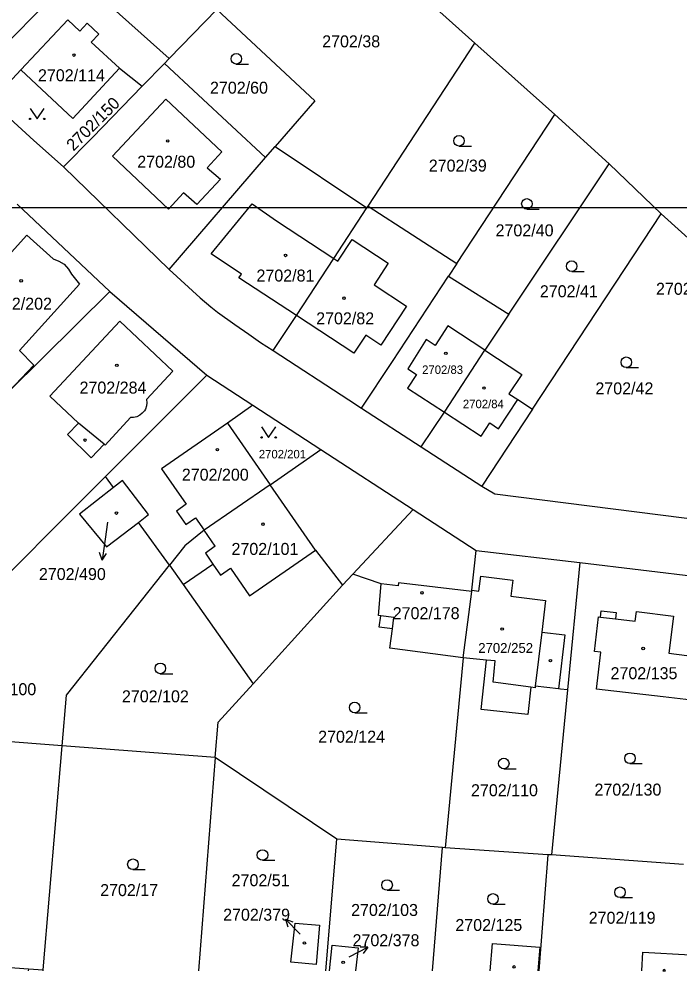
# Model space of a CAD drawing. Extents: x -496682 to -495907, y -1088575 to -1088018.
# Drawn here: x -496493 to -496399.3, y -1088569.4 to -1088434.5 of the extents above; entities that cross this region are included whole.
import ezdxf

# ---------------------------------------------------------------- set-up
doc = ezdxf.new("R2010")
doc.units = 0
for name, color, linetype in [('Hranice parcel', 7, 'Continuous'), ('Parcelní čísla', 7, 'Continuous'), ('Pop  PČ popisy', 7, 'Continuous'), ('Vnitřní kresba', 7, 'Continuous'), ('Vrstva 63', 7, 'Continuous'), ('Značky budov', 7, 'Continuous'), ('Značky kultur', 7, 'Continuous')]:
    doc.layers.add(name, color=color, linetype=linetype)

msp = doc.modelspace()

# ---------------------------------------------------------------- linework, layer by layer
at = {"layer": 'Hranice parcel'}
for p, q in [((-496428.41, -1088437.89), (-496447.16, -1088420.94)), ((-496471.71, -1088440.06), (-496485.14, -1088428.06)), ((-496485.53, -1088428.46), (-496500.3, -1088443.59)), ((-496464.95, -1088433.12), (-496471.71, -1088440.06)), ((-496443.54, -1088460.99), (-496428.41, -1088437.89)), ((-496417.08, -1088447.98), (-496428.41, -1088437.89)), ((-496471.71, -1088440.06), (-496472.38, -1088440.74)), ((-496472.38, -1088440.74), (-496475.55, -1088443.98)), ((-496472.38, -1088440.74), (-496458.05, -1088454.11)), ((-496430.97, -1088469.11), (-496417.08, -1088447.98)), ((-496409.38, -1088454.98), (-496417.08, -1088447.98)), ((-496458.05, -1088454.11), (-496456.7, -1088452.55)), ((-496456.7, -1088452.55), (-496443.69, -1088461.21)), ((-496471.75, -1088469.95), (-496458.05, -1088454.11)), ((-496423.57, -1088476.29), (-496409.38, -1088454.98)), ((-496401.99, -1088462.09), (-496409.38, -1088454.98)), ((-496486.71, -1088455.42), (-496471.75, -1088469.95)), ((-496493.26, -1088460.72), (-496480.12, -1088473.09)), ((-496443.69, -1088461.21), (-496443.54, -1088460.99)), ((-496443.54, -1088460.99), (-496430.97, -1088469.11)), ((-496420.23, -1088489.77), (-496401.99, -1088462.09)), ((-496390.64, -1088472.36), (-496401.99, -1088462.09)), ((-496430.97, -1088469.11), (-496432.15, -1088470.9)), ((-496432.15, -1088470.9), (-496423.57, -1088476.29)), ((-496480.12, -1088473.09), (-496466.41, -1088484.97)), ((-496423.57, -1088476.29), (-496426.98, -1088481.41)), ((-496480.76, -1088499.32), (-496466.41, -1088484.97)), ((-496466.41, -1088484.97), (-496459.85, -1088489.23)), ((-496459.85, -1088489.23), (-496450.23, -1088495.49)), ((-496444.46, -1088489.63), (-496436, -1088495.13)), ((-496420.23, -1088489.77), (-496427.43, -1088500.69)), ((-496457.42, -1088500.49), (-496450.23, -1088495.49)), ((-496450.23, -1088495.49), (-496437.15, -1088504)), ((-496436, -1088495.13), (-496427.43, -1088500.69)), ((-496479.61, -1088500.91), (-496480.76, -1088499.32)), ((-496445.71, -1088513.16), (-496437.15, -1088504)), ((-496437.15, -1088504), (-496428.21, -1088509.82)), ((-496471.67, -1088511.91), (-496476.06, -1088505.83)), ((-496469.49, -1088509.17), (-496471.67, -1088511.91)), ((-496428.21, -1088509.82), (-496413.5, -1088511.53)), ((-496413.5, -1088511.53), (-496415.26, -1088529.6)), ((-496413.5, -1088511.53), (-496394.97, -1088513.78)), ((-496441.68, -1088514.55), (-496445.71, -1088513.16)), ((-496430.07, -1088525.02), (-496432.62, -1088551.99)), ((-496415.26, -1088529.6), (-496417.53, -1088552.98)), ((-496486.91, -1088537.52), (-496508.81, -1088535.85)), ((-496489.6, -1088569.29), (-496486.91, -1088537.52)), ((-496465.19, -1088539.18), (-496486.91, -1088537.52)), ((-496465.19, -1088539.18), (-496467.58, -1088569.45)), ((-496447.96, -1088550.78), (-496465.19, -1088539.18)), ((-496449.5, -1088569.45), (-496447.96, -1088550.78)), ((-496433, -1088551.96), (-496447.96, -1088550.78)), ((-496434.4, -1088569.45), (-496433, -1088551.96)), ((-496432.62, -1088551.99), (-496433, -1088551.96)), ((-496418.06, -1088552.96), (-496432.62, -1088551.99)), ((-496418.06, -1088552.96), (-496419.34, -1088569.45)), ((-496417.53, -1088552.98), (-496418.06, -1088552.96)), ((-496398.8, -1088554.34), (-496417.53, -1088552.98)), ((-496489.61, -1088569.45), (-496489.6, -1088569.29))]:
    msp.add_line(p, q, dxfattribs=at)
for points in [[(-496464.95, -1088433.12), (-496451.1, -1088446.07), (-496456.7, -1088452.55)], [(-496497, -1088446.21), (-496492.75, -1088441.67), (-496485.37, -1088448.58), (-496478.75, -1088441.43), (-496475.55, -1088443.98)], [(-496475.55, -1088443.98), (-496482.58, -1088451.24), (-496486.71, -1088455.42)], [(-496486.71, -1088455.42), (-496490.9, -1088451.69), (-496494.87, -1088448.06), (-496497, -1088446.21)], [(-496456.97, -1088481.48), (-496453.7, -1088476.48), (-496448.39, -1088468.4), (-496443.69, -1088461.21)], [(-496471.75, -1088469.95), (-496467.34, -1088473.97), (-496465.8, -1088475.27), (-496464.87, -1088476.01), (-496462.43, -1088477.79), (-496460.45, -1088479.15), (-496458.77, -1088480.31), (-496456.97, -1088481.48)], [(-496444.46, -1088489.63), (-496440.08, -1088483), (-496432.15, -1088470.9)], [(-496480.12, -1088473.09), (-496494.39, -1088487.23), (-496495.38, -1088488.23)], [(-496477.23, -1088490.95), (-496480.8, -1088494.89), (-496480.96, -1088494.74), (-496482.79, -1088496.66), (-496486.16, -1088493.39), (-496484.58, -1088491.75), (-496488.65, -1088487.95), (-496478.73, -1088477.31), (-496471.2, -1088484.41), (-496474.93, -1088488.41)], [(-496456.97, -1088481.48), (-496446.26, -1088488.46), (-496444.46, -1088489.63)], [(-496436, -1088495.13), (-496432.72, -1088490.21), (-496426.98, -1088481.41)], [(-496426.98, -1088481.41), (-496421.75, -1088484.85), (-496423.56, -1088487.61), (-496422.3, -1088488.43), (-496420.23, -1088489.77)], [(-496474.93, -1088488.41), (-496474.89, -1088488.87), (-496474.94, -1088489.33), (-496475.1, -1088489.76), (-496475.24, -1088490.01), (-496475.54, -1088490.37), (-496475.9, -1088490.65), (-496476.32, -1088490.85), (-496476.77, -1088490.95), (-496477.23, -1088490.95)], [(-496459.85, -1088489.23), (-496463.48, -1088491.75), (-496457.42, -1088500.49)], [(-496507.29, -1088518.51), (-496500.51, -1088519.07), (-496480.76, -1088499.32)], [(-496479.61, -1088500.91), (-496484.42, -1088504.69), (-496480.61, -1088509.32), (-496476.06, -1088505.83)], [(-496476.06, -1088505.83), (-496474.64, -1088504.74), (-496478.32, -1088499.89), (-496479.61, -1088500.91)], [(-496457.42, -1088500.49), (-496466.76, -1088506.96), (-496469.49, -1088509.17)], [(-496465.53, -1088511.75), (-496464.43, -1088513.34), (-496463.02, -1088512.35), (-496460.32, -1088516.24), (-496450.98, -1088509.77), (-496457.42, -1088500.49)], [(-496427.43, -1088500.69), (-496425.57, -1088501.8), (-496381.96, -1088507.33)], [(-496430.07, -1088525.02), (-496428.84, -1088515.66), (-496428.82, -1088515.46), (-496428.21, -1088509.82)], [(-496471.67, -1088511.91), (-496469.73, -1088514.66), (-496465.53, -1088511.75)], [(-496486.91, -1088537.52), (-496486.26, -1088530.32), (-496471.67, -1088511.91)], [(-496465.19, -1088539.18), (-496464.79, -1088534.19), (-496459.83, -1088528.71), (-496447.17, -1088514.73), (-496445.71, -1088513.16)], [(-496430.07, -1088525.02), (-496440.44, -1088523.65), (-496440.09, -1088520.95), (-496441.94, -1088520.7), (-496441.73, -1088519.1), (-496442.06, -1088519.05), (-496441.68, -1088514.55)], [(-496401.7, -1088530.59), (-496411.17, -1088529.49), (-496410.56, -1088524.24), (-496411.46, -1088524.14), (-496410.89, -1088519.24), (-496410.59, -1088519.28), (-496410.48, -1088518.4), (-496408.38, -1088518.63), (-496408.48, -1088519.52), (-496405.68, -1088519.85), (-496405.48, -1088518.47), (-496400.24, -1088519.14), (-496400.91, -1088524.37), (-496396.87, -1088524.88), (-496397.69, -1088531.06), (-496401.7, -1088530.59)], [(-496415.26, -1088529.6), (-496416.28, -1088529.48), (-496416.53, -1088529.45), (-496419.84, -1088529.05), (-496419.87, -1088529.29), (-496420.45, -1088529.21), (-496420.88, -1088533.09), (-496427.49, -1088532.36), (-496426.73, -1088525.36), (-496430.07, -1088525.02)], [(-496454.49, -1088568.22), (-496453.89, -1088562.66), (-496450.42, -1088562.94), (-496450.89, -1088568.53), (-496454.49, -1088568.22)], [(-496449.01, -1088569.45), (-496448.61, -1088565.79)], [(-496448.61, -1088565.79), (-496444.95, -1088566.18), (-496445.31, -1088569.45)], [(-496426.22, -1088569.45), (-496425.91, -1088565.54), (-496419.2, -1088566.07)], [(-496419.2, -1088566.07), (-496419.47, -1088569.45)], [(-496404.72, -1088569.45), (-496404.57, -1088566.8), (-496397.81, -1088567.16), (-496397.94, -1088569.45)], [(-496502.29, -1088569.45), (-496502.24, -1088568.24), (-496496.2, -1088568.8), (-496491.67, -1088569.13), (-496489.6, -1088569.29)]]:
    msp.add_lwpolyline(points, dxfattribs=at)
at = {"layer": 'Pop  PČ popisy'}
for p, q in [((-496480.45, -1088505.79), (-496480.81, -1088508.21)), ((-496480.81, -1088508.21), (-496481.23, -1088511.18)), ((-496481.23, -1088511.18), (-496481.58, -1088510.12)), ((-496481.23, -1088511.18), (-496480.59, -1088510.26)), ((-496453.14, -1088564.24), (-496455.26, -1088562.12)), ((-496455.26, -1088562.12), (-496454.2, -1088562.47)), ((-496455.26, -1088562.12), (-496454.91, -1088563.18)), ((-496446.22, -1088567.44), (-496443.55, -1088566.08)), ((-496443.55, -1088566.08), (-496444.67, -1088566.09)), ((-496443.55, -1088566.08), (-496444.21, -1088566.98))]:
    msp.add_line(p, q, dxfattribs=at)
at = {"layer": 'Vnitřní kresba'}
for p, q in [((-496486.09, -1088434.56), (-496492.75, -1088441.67)), ((-496484.4, -1088436.16), (-496486.09, -1088434.56)), ((-496483.35, -1088435.06), (-496484.4, -1088436.16)), ((-496481.7, -1088436.58), (-496483.35, -1088435.06)), ((-496482.76, -1088437.72), (-496481.7, -1088436.58)), ((-496478.75, -1088441.43), (-496482.76, -1088437.72)), ((-496479.76, -1088453.88), (-496472.22, -1088445.82)), ((-496472.22, -1088445.82), (-496464.24, -1088453.27)), ((-496464.24, -1088453.27), (-496466.36, -1088455.54)), ((-496471.83, -1088461.4), (-496479.76, -1088453.88)), ((-496466.36, -1088455.54), (-496464.46, -1088457.16)), ((-496464.46, -1088457.16), (-496467.81, -1088460.76)), ((-496469.7, -1088459.11), (-496471.83, -1088461.4)), ((-496467.81, -1088460.76), (-496469.7, -1088459.11)), ((-496465.78, -1088467.74), (-496459.95, -1088460.67)), ((-496459.95, -1088460.67), (-496456.51, -1088463.09)), ((-496456.51, -1088463.09), (-496448.39, -1088468.4)), ((-496495.33, -1088468.94), (-496491.92, -1088465.12)), ((-496491.92, -1088465.12), (-496488.18, -1088468.46)), ((-496447.8, -1088468.79), (-496445.8, -1088465.72)), ((-496445.8, -1088465.72), (-496440.68, -1088469.07)), ((-496488.18, -1088468.46), (-496487.38, -1088468.79)), ((-496461.49, -1088470.63), (-496465.78, -1088467.74)), ((-496448.39, -1088468.4), (-496447.8, -1088468.79)), ((-496487.38, -1088468.79), (-496486.63, -1088469.24)), ((-496486.63, -1088469.24), (-496485.98, -1088469.91)), ((-496485.98, -1088469.91), (-496485.56, -1088470.63)), ((-496440.68, -1088469.07), (-496442.69, -1088472.14)), ((-496485.56, -1088470.63), (-496484.43, -1088472.03)), ((-496461.86, -1088471.14), (-496461.49, -1088470.63)), ((-496453.7, -1088476.48), (-496461.86, -1088471.14)), ((-496484.43, -1088472.03), (-496492.96, -1088481.47)), ((-496442.69, -1088472.14), (-496438.1, -1088475.15)), ((-496438.1, -1088475.15), (-496441.72, -1088480.68)), ((-496445.54, -1088481.82), (-496453.7, -1088476.48)), ((-496432.21, -1088477.96), (-496434.04, -1088480.74)), ((-496426.98, -1088481.41), (-496432.21, -1088477.96)), ((-496443.85, -1088479.3), (-496445.54, -1088481.82)), ((-496441.72, -1088480.68), (-496443.85, -1088479.3)), ((-496435.28, -1088479.92), (-496437.91, -1088484.07)), ((-496434.04, -1088480.74), (-496435.28, -1088479.92)), ((-496492.96, -1088481.47), (-496490.92, -1088483.54)), ((-496494.39, -1088487.23), (-496490.92, -1088483.54)), ((-496437.91, -1088484.07), (-496436.67, -1088484.88)), ((-496436.67, -1088484.88), (-496437.93, -1088486.8)), ((-496437.93, -1088486.8), (-496432.72, -1088490.21)), ((-496425.03, -1088492.56), (-496422.3, -1088488.43)), ((-496432.72, -1088490.21), (-496427.51, -1088493.61)), ((-496480.96, -1088494.74), (-496484.58, -1088491.75)), ((-496463.48, -1088491.75), (-496472.82, -1088498.22)), ((-496427.51, -1088493.61), (-496426.29, -1088491.74)), ((-496426.29, -1088491.74), (-496425.03, -1088492.56)), ((-496472.82, -1088498.22), (-496469.32, -1088503.27)), ((-496469.32, -1088503.27), (-496470.71, -1088504.23)), ((-496470.71, -1088504.23), (-496469.38, -1088506.14)), ((-496469.38, -1088506.14), (-496467.99, -1088505.18)), ((-496467.99, -1088505.18), (-496466.76, -1088506.96)), ((-496465.19, -1088509.22), (-496466.76, -1088506.96)), ((-496465.19, -1088509.22), (-496466.6, -1088510.2)), ((-496466.6, -1088510.2), (-496465.53, -1088511.75)), ((-496450.98, -1088509.77), (-496447.17, -1088514.73)), ((-496439.28, -1088514.85), (-496441.68, -1088514.55)), ((-496439.23, -1088514.41), (-496439.28, -1088514.85)), ((-496428.84, -1088515.66), (-496439.23, -1088514.41)), ((-496427.81, -1088515.59), (-496427.55, -1088513.46)), ((-496427.55, -1088513.46), (-496422.99, -1088514.03)), ((-496422.99, -1088514.03), (-496423.3, -1088516.32)), ((-496469.73, -1088514.66), (-496459.83, -1088528.71)), ((-496428.82, -1088515.46), (-496427.81, -1088515.59)), ((-496423.3, -1088516.32), (-496418.38, -1088516.91)), ((-496418.38, -1088516.91), (-496418.92, -1088521.38)), ((-496439.87, -1088519.34), (-496441.73, -1088519.1)), ((-496440.09, -1088520.95), (-496439.87, -1088519.34)), ((-496410.59, -1088519.28), (-496408.48, -1088519.52)), ((-496418.92, -1088521.38), (-496419.84, -1088529.05)), ((-496491.67, -1088569.13), (-496491.7, -1088569.45))]:
    msp.add_line(p, q, dxfattribs=at)
for points in [[(-496418.92, -1088521.38), (-496415.65, -1088521.78), (-496416.53, -1088529.45)], [(-496420.45, -1088529.21), (-496425.81, -1088528.51), (-496425.52, -1088525.48), (-496426.73, -1088525.36)]]:
    msp.add_lwpolyline(points, dxfattribs=at)
at = {"layer": 'Vrstva 63'}
msp.add_lwpolyline([(-496137.35, -1088164.24), (-496137.35, -1088461.24), (-496557.35, -1088461.24), (-496557.35, -1088164.24)], close=True, dxfattribs=at)
at = {"layer": 'Značky budov'}
msp.add_line((-496401.73, -1088569.45), (-496401.38, -1088569.45), dxfattribs=at)
for centre in [(-496485.22, -1088439.57), (-496471.93, -1088451.74), (-496455.23, -1088467.98), (-496492.7, -1088471.58), (-496446.95, -1088474.04), (-496432.51, -1088481.85), (-496479.14, -1088483.56), (-496427.11, -1088486.78), (-496483.65, -1088494.17), (-496464.89, -1088495.53), (-496479.2, -1088504.52), (-496458.43, -1088506.09), (-496435.9, -1088515.82), (-496424.53, -1088520.96), (-496404.54, -1088523.72), (-496417.68, -1088525.45), (-496452.55, -1088565.47), (-496447.06, -1088568.22), (-496422.84, -1088568.87)]:
    msp.add_circle(centre, 0.175, dxfattribs=at)
msp.add_arc((-496401.56, -1088569.43), 0.175, 353.714, 186.286, dxfattribs=at)
at = {"layer": 'Značky kultur'}
for p, q in [((-496462.21, -1088440.84), (-496460.46, -1088440.84)), ((-496430.64, -1088452.47), (-496428.89, -1088452.47)), ((-496421.02, -1088461.42), (-496419.27, -1088461.42)), ((-496414.67, -1088470.25), (-496412.92, -1088470.25)), ((-496406.93, -1088483.88), (-496405.18, -1088483.88)), ((-496472.98, -1088527.29), (-496471.23, -1088527.29)), ((-496445.43, -1088532.84), (-496443.68, -1088532.84)), ((-496406.41, -1088540.04), (-496404.66, -1088540.04)), ((-496424.3, -1088540.78), (-496422.55, -1088540.78)), ((-496476.86, -1088555.07), (-496475.11, -1088555.07)), ((-496458.5, -1088553.76), (-496456.75, -1088553.76)), ((-496440.84, -1088558.01), (-496439.09, -1088558.01)), ((-496407.82, -1088559.04), (-496406.07, -1088559.04)), ((-496425.83, -1088559.98), (-496424.08, -1088559.98))]:
    msp.add_line(p, q, dxfattribs=at)
for points in [[(-496491.43, -1088447.12), (-496490.43, -1088448.62), (-496489.43, -1088447.12)], [(-496458.63, -1088492.29), (-496457.63, -1088493.79), (-496456.63, -1088492.29)]]:
    msp.add_lwpolyline(points, dxfattribs=at)
for centre, radius in [((-496462.21, -1088440.09), 0.75), ((-496491.43, -1088448.62), 0.1), ((-496489.43, -1088448.62), 0.1), ((-496430.64, -1088451.72), 0.75), ((-496421.02, -1088460.67), 0.75), ((-496414.67, -1088469.5), 0.75), ((-496406.93, -1088483.13), 0.75), ((-496458.63, -1088493.79), 0.1), ((-496456.63, -1088493.79), 0.1), ((-496472.98, -1088526.54), 0.75), ((-496445.43, -1088532.09), 0.75), ((-496406.41, -1088539.29), 0.75), ((-496424.3, -1088540.03), 0.75), ((-496458.5, -1088553.01), 0.75), ((-496476.86, -1088554.32), 0.75), ((-496440.84, -1088557.26), 0.75), ((-496407.82, -1088558.29), 0.75), ((-496425.83, -1088559.23), 0.75)]:
    msp.add_circle(centre, radius, dxfattribs=at)

# ---------------------------------------------------------------- texts
at = {"layer": 'Parcelní čísla'}
for s, height, p in [('2702/38', 1.7, (-496450.04, -1088438.47)), ('2702/114', 1.7, (-496490.32, -1088443.28)), ('2702/60', 1.7, (-496465.94, -1088445.04)), ('2702/80', 1.7, (-496476.25, -1088455.54)), ('2702/39', 1.7, (-496434.93, -1088456.09)), ('2702/40', 1.7, (-496425.46, -1088465.27)), ('2702/81', 1.7, (-496459.35, -1088471.68)), ('2702/41', 1.7, (-496419.18, -1088473.91)), ('2702/487', 1.7, (-496402.72, -1088473.56)), ('2702/202', 1.7, (-496497.82, -1088475.67)), ('2702/82', 1.7, (-496450.89, -1088477.75)), ('2702/83', 1.2, (-496435.87, -1088484.78)), ('2702/284', 1.7, (-496484.43, -1088487.57)), ('2702/42', 1.7, (-496411.31, -1088487.68)), ('2702/84', 1.2, (-496430.09, -1088489.64)), ('2702/201', 1.2, (-496459.02, -1088496.76)), ('2702/200', 1.7, (-496469.93, -1088499.92)), ('2702/101', 1.7, (-496462.89, -1088510.45)), ('2702/490', 1.7, (-496490.19, -1088514.01)), ('2702/178', 1.7, (-496440.04, -1088519.56)), ('2702/252', 1.394, (-496427.92, -1088524.34)), ('2702/135', 1.7, (-496409.16, -1088528.07)), ('2702/100', 1.7, (-496500.05, -1088530.34)), ('2702/102', 1.7, (-496478.42, -1088531.35)), ('2702/124', 1.7, (-496450.61, -1088537.08)), ('2702/110', 1.7, (-496428.94, -1088544.67)), ('2702/130', 1.7, (-496411.44, -1088544.58)), ('2702/51', 1.7, (-496462.87, -1088557.43)), ('2702/17', 1.7, (-496481.51, -1088558.83)), ('2702/103', 1.7, (-496445.94, -1088561.65)), ('2702/379', 1.7, (-496464.08, -1088562.32)), ('2702/119', 1.7, (-496412.26, -1088562.75)), ('2702/125', 1.7, (-496431.16, -1088563.78)), ('2702/378', 1.7, (-496445.73, -1088565.94))]:
    msp.add_text(s, height=height, dxfattribs=at).set_placement(p)
msp.add_text('2702/150', height=1.7, rotation=45, dxfattribs=at).set_placement((-496485.28, -1088453.27))

doc.saveas('drawing.dxf')
